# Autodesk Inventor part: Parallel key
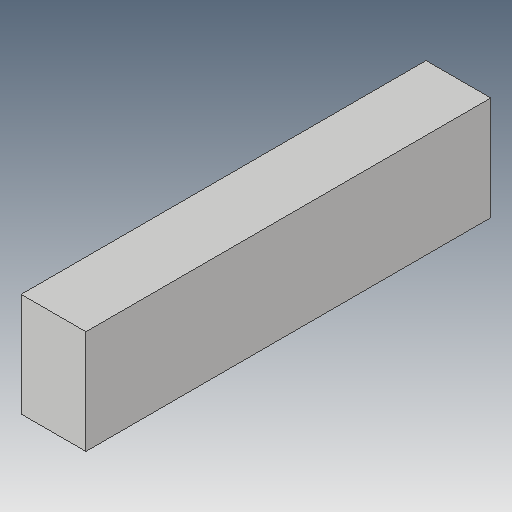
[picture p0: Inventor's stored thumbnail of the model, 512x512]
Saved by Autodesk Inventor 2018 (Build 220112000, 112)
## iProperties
Created: 2016-05
Part Number: Parallel key
Material: Generic
Document SubType Name: Modeling
Designer: CADCIM
Density: 1 g/cm^3
Appearance: Default
Author: CADCIM
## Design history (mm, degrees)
sketch "Sketch1"
  geometry: L1 (0, 0)-(16, 0); L2 (16, 0)-(16, -62.5); L3 (16, -62.5)-(0, -62.5); L4 (0, -62.5)-(0, 0)
  constraints: 8 end point, 2 parallel, 1 horizontal, 1 perpendicular
  dimensions: "d0" = 62.5 distance of L3.end L1.start; "d1" = 16 distance of L2.end L3.end
extrude "Extrusion1" new body sketch "Sketch1" distance "d2" = 10; taper "d3" = 0 deg
body "Solid1"
